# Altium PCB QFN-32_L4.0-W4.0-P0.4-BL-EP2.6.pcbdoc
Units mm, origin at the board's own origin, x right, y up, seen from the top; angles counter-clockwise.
Board outline 17.1 x 17.5 mm, 2 copper layers (Top Layer, Bottom Layer), stack 0 mm thick; 1 components, 0 nets, 33 pads, 0 vias.
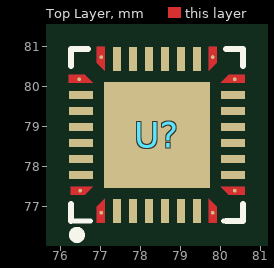
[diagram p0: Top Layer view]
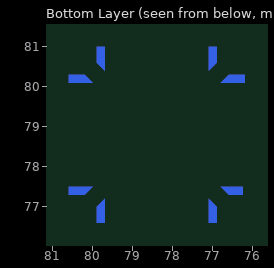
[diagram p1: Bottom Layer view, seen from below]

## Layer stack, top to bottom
Top Layer: signal copper (thickness not stored)
Bottom Layer: signal copper (thickness not stored)

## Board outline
86.95,69.85 69.85,69.85 69.85,87.35 86.95,87.35

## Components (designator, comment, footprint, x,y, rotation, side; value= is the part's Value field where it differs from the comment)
U? "" QFN-32_L4.0-W4.0-P0.4-BL-EP2.6 78.4,78.8 r0 top

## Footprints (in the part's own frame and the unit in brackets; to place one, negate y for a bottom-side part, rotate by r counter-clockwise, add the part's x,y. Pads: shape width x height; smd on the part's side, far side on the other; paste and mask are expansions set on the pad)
QFN-32_L4.0-W4.0-P0.4-BL-EP2.6 [mm]
  round 0.093 smd: 1(-1.394,-1.947) 8(1.393,-1.947) 9(1.947,-1.393) 16(1.947,1.393) 17(1.394,1.947) 24(-1.393,1.947) 25(-1.947,1.394) 32(-1.921,-1.392)
  rect 0.2x0.6 smd paste-100 mask+0.05: 2(-1,-1.9) 3(-0.6,-1.9) 4(-0.2,-1.9) 5(0.2,-1.9) 6(0.6,-1.9) 7(1,-1.9) 18(1,1.9) 19(0.6,1.9) 20(0.2,1.9) 21(-0.2,1.9) 22(-0.6,1.9) 23(-1,1.9)
  rect 0.6x0.2 smd paste-100 mask+0.05: 10(1.9,-1) 11(1.9,-0.6) 12(1.9,-0.2) 13(1.9,0.2) 14(1.9,0.6) 15(1.9,1) 26(-1.9,1) 27(-1.9,0.6) 28(-1.9,0.2) 29(-1.9,-0.2) 30(-1.9,-0.6) 31(-1.9,-1)
  rect 2.642x2.642 smd paste-100 mask+0.05: 33(0,0)
  Top Layer region: -1.5,1.8 -1.5,2.2 -1.3,2.2 -1.3,1.6
  Top Layer region: 1.5,-1.8 1.5,-2.2 1.3,-2.2 1.3,-1.6
  Top Layer region: 1.6,-1.3 2.2,-1.3 2.2,-1.5 1.8,-1.5
  Top Layer region: 1.8,1.5 2.2,1.5 2.2,1.3 1.6,1.3
  Top Layer region: 1.3,1.6 1.3,2.2 1.5,2.2 1.5,1.8
  Top Layer region: -1.8,-1.5 -2.15,-1.5 -2.15,-1.3 -1.6,-1.3
  Top Layer region: -1.3,-1.6 -1.3,-2.2 -1.5,-2.2 -1.5,-1.8
  Top Layer region: -1.6,1.3 -2.2,1.3 -2.2,1.5 -1.8,1.5
  Bottom Layer region: -1.5,1.8 -1.5,2.2 -1.3,2.2 -1.3,1.6
  Bottom Layer region: 1.5,-1.8 1.5,-2.2 1.3,-2.2 1.3,-1.6
  Bottom Layer region: 1.6,-1.3 2.2,-1.3 2.2,-1.5 1.8,-1.5
  Bottom Layer region: 1.8,1.5 2.2,1.5 2.2,1.3 1.6,1.3
  Bottom Layer region: 1.3,1.6 1.3,2.2 1.5,2.2 1.5,1.8
  Bottom Layer region: -1.8,-1.5 -2.15,-1.5 -2.15,-1.3 -1.6,-1.3
  Bottom Layer region: -1.3,-1.6 -1.3,-2.2 -1.5,-2.2 -1.5,-1.8
  Bottom Layer region: -1.6,1.3 -2.2,1.3 -2.2,1.5 -1.8,1.5
  Multi-Layer region: -1.5,1.8 -1.5,2.2 -1.3,2.2 -1.3,1.6
  Multi-Layer region: 1.5,-1.8 1.5,-2.2 1.3,-2.2 1.3,-1.6
  Multi-Layer region: 1.6,-1.3 2.2,-1.3 2.2,-1.5 1.8,-1.5
  Multi-Layer region: 1.8,1.5 2.2,1.5 2.2,1.3 1.6,1.3
  Multi-Layer region: 1.3,1.6 1.3,2.2 1.5,2.2 1.5,1.8
  Multi-Layer region: -1.8,-1.5 -2.15,-1.5 -2.15,-1.3 -1.6,-1.3
  Multi-Layer region: -1.3,-1.6 -1.3,-2.2 -1.5,-2.2 -1.5,-1.8
  Multi-Layer region: -1.6,1.3 -2.2,1.3 -2.2,1.5 -1.8,1.5
  silkscreen extent -2.15,-2.6 2.15,2.15

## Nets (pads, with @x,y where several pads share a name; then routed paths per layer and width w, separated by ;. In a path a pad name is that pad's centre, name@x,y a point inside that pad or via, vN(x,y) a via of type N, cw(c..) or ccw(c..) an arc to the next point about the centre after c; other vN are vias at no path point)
pads on no net: U?.1 U?.2 U?.3 U?.4 U?.5 U?.6 U?.7 U?.8 U?.9 U?.10 U?.11 U?.12 U?.13 U?.14 U?.15 U?.16 U?.17 U?.18 U?.19 U?.20 U?.21 U?.22 U?.23 U?.24 U?.25 U?.26 U?.27 U?.28 U?.29 U?.30 U?.31 U?.32 U?.33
